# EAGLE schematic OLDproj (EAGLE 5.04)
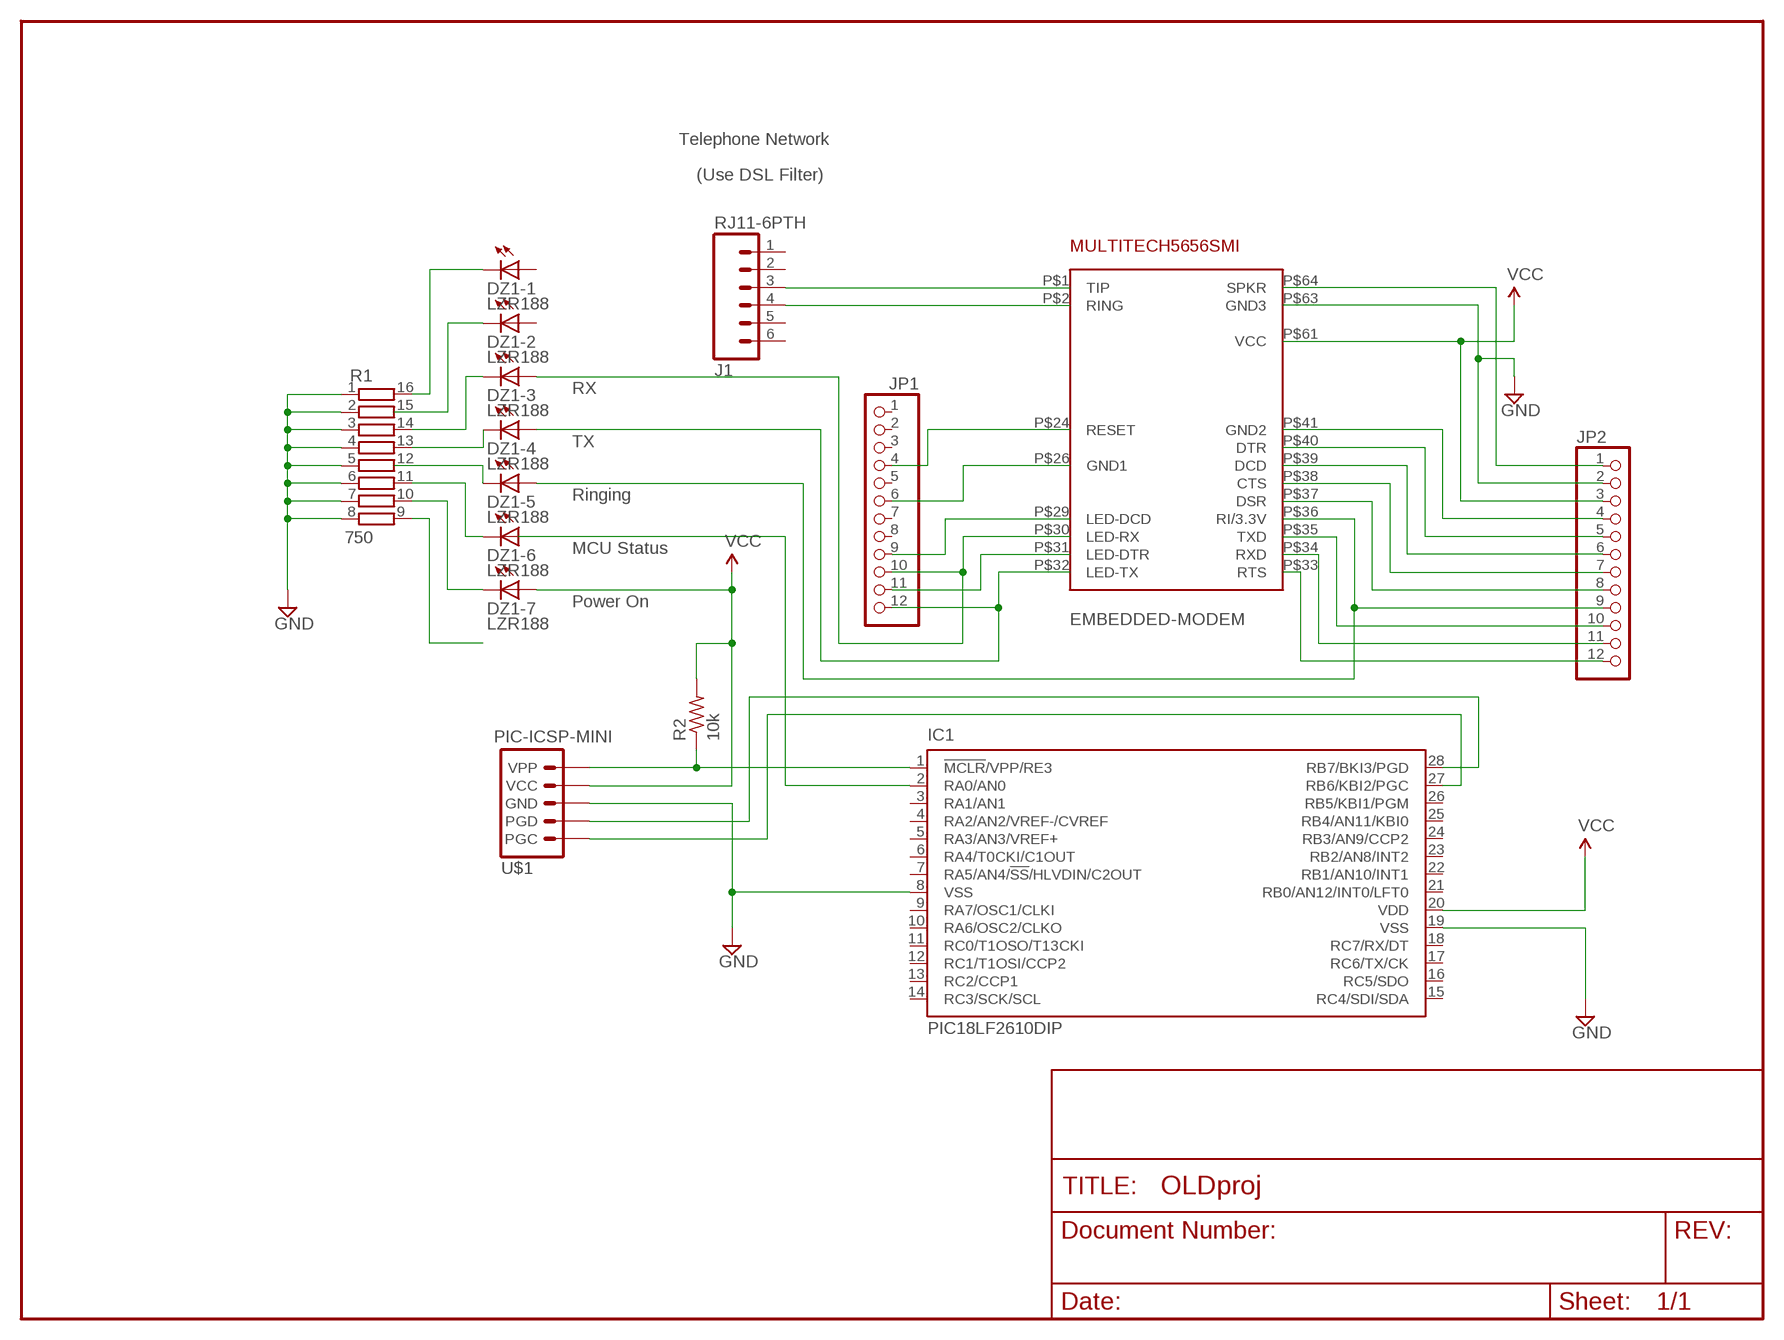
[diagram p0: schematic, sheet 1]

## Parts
DZ1  LZR188  [LZR188]
EMBEDDED-MODEM  MULTITECH5656SMI  [64DIP]
IC1  PIC18LF2610DIP  [DIL28-3]
J1  RJ11-6PTH  [RJ11-6]
JP1  PINHD-1X12  [1X12]
JP2  PINHD-1X12  [1X12]
R1  750  2NBS16-8  [SO16]
R2  10k  R-US_V234/12  [V234/12]
U$1  PIC-ICSP-MINI  [PIC-ICSP-MINI]

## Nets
GND: EMBEDDED-MODEM.P$63(GND3) IC1.8(VSS) IC1.19(VSS) JP2.2 R1.1 R1.2 R1.3 R1.4 R1.5 R1.6 R1.7 R1.8 U$1.3(GND)
N$1: EMBEDDED-MODEM.P$1(TIP) J1.3
N$2: EMBEDDED-MODEM.P$2(RING) J1.4
N$3: EMBEDDED-MODEM.P$24(RESET) JP1.4
N$4: EMBEDDED-MODEM.P$26(GND1) JP1.6
N$5: DZ1.A4(-4:A) EMBEDDED-MODEM.P$32(LED-TX) JP1.12
N$6: EMBEDDED-MODEM.P$31(LED-DTR) JP1.11
N$7: DZ1.A3(-3:A) EMBEDDED-MODEM.P$30(LED-RX) JP1.10
N$8: EMBEDDED-MODEM.P$29(LED-DCD) JP1.9
N$9: EMBEDDED-MODEM.P$64(SPKR) JP2.1
N$10: IC1.1(!MCLR!/VPP/RE3) R2.1 U$1.1(VPP)
N$11: IC1.28(RB7/BKI3/PGD) U$1.4(PGD)
N$12: IC1.27(RB6/KBI2/PGC) U$1.5(PGC)
N$13: DZ1.K1(-1:C) R1.16
N$14: DZ1.K2(-2:C)
N$15: DZ1.K3(-3:C) R1.14
N$16: DZ1.K4(-4:C) R1.13
N$17: DZ1.K5(-5:C)
N$18: DZ1.K6(-6:C) R1.11
N$19: DZ1.K7(-7:C) R1.10
N$20: R1.9
N$21: IC1.2(RA0/AN0)
N$22: EMBEDDED-MODEM.P$33(RTS) JP2.12
N$23: EMBEDDED-MODEM.P$34(RXD) JP2.11
N$24: EMBEDDED-MODEM.P$41(GND2) JP2.4
N$25: EMBEDDED-MODEM.P$40(DTR) JP2.5
N$26: EMBEDDED-MODEM.P$39(DCD) JP2.6
N$27: EMBEDDED-MODEM.P$35(TXD) JP2.10
N$28: DZ1.A5(-5:A) EMBEDDED-MODEM.P$36(RI/3.3V) JP2.9
N$29: EMBEDDED-MODEM.P$37(DSR) JP2.8
N$30: EMBEDDED-MODEM.P$38(CTS) JP2.7
VCC: DZ1.A7(-7:A) EMBEDDED-MODEM.P$61(VCC) IC1.20(VDD) JP2.3 R2.2 U$1.2(VCC)
Unconnected: DZ1.A1(-1:A) DZ1.A2(-2:A) DZ1.A6(-6:A) DZ1.A8(-8:A) DZ1.K8(-8:C) IC1.3(RA1/AN1) IC1.4(RA2/AN2/VREF-/CVREF) IC1.5(RA3/AN3/VREF+) IC1.6(RA4/T0CKI/C1OUT) IC1.7(RA5/AN4/!SS!/HLVDIN/C2OUT) IC1.9(RA7/OSC1/CLKI) IC1.10(RA6/OSC2/CLKO) IC1.11(RC0/T1OSO/T13CKI) IC1.12(RC1/T1OSI/CCP2) IC1.13(RC2/CCP1) IC1.14(RC3/SCK/SCL) IC1.15(RC4/SDI/SDA) IC1.16(RC5/SDO) IC1.17(RC6/TX/CK) IC1.18(RC7/RX/DT) IC1.21(RB0/AN12/INT0/LFT0) IC1.22(RB1/AN10/INT1) IC1.23(RB2/AN8/INT2) IC1.24(RB3/AN9/CCP2) IC1.25(RB4/AN11/KBI0) IC1.26(RB5/KBI1/PGM) J1.1 J1.2 J1.5 J1.6 JP1.1 JP1.2 JP1.3 JP1.5 JP1.7 JP1.8 R1.12 R1.15

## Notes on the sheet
- Telephone Network
- (Use DSL Filter)
- RX
- TX
- Ringing
- MCU Status
- Power On

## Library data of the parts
DZ1 = trl:LZR188: LED BLOCK 5 LEDs, Siemens
EMBEDDED-MODEM = trl:MULTITECH5656SMI
IC1 = trl:PIC18LF2610: PIC18LF2610 28-Pin, No USB or EEPROM
J1 = SparkFun:RJ11-6: RJ11 Jack Simple 6 pin RJ11 jack. Commonly found on CAT3 devices and Microchip programmers. SKU: PRT-00132
JP1 JP2 = pinhead:PINHD-1X12: PIN HEADER
R1 = resistor-bourns:2NBS16-8: BOURNS RESISTOR NETWORK
R2 = rcl:R-US_: RESISTOR, American symbol
U$1 = SparkFun:PIC-ICSP-MINI: PIC-ICSP-Mini Miniature 5-pin connection for temporary programming of PICs. Use this device in your design to save space. Program the PIC with this adapter Spark Fun Electronics SKU : BOB-00194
